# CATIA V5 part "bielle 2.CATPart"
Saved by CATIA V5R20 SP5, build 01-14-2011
Part number: bielle 2
Bounding box of the stored display mesh (mm): x -831.882 to 4290.352, y -250 to 250, z 2689.909 to 7173.528
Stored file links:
  M:\EU_thinkMotion\IAO_2010\iao\IAO_MMS_Groupe1\Problemes\gduval\Gduval\train d'aterrissage squelette + piece kinematic\bielle 2.CATPart
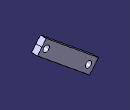
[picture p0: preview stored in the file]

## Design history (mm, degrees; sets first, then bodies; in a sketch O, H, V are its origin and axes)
Body1 (main body)
  Point1: stored without definition
  Point2: stored without definition
  Sketch1 on zx-plane, origin (0, 0, 0), H (-1, 0, 0), V (0, 0, 1)
    axis line L1 (-3755.1482, 6585.784) -> (369.2272, 3218.4199)
    reference projected point E1 (0, 3519.877) from Point1
    reference projected point E2 (-3562.187, 6428.24) from Point2
    line L2 (831.8815, 3594.3707) -> (-3551.9, 7173.5281)
    point P3 (831.8815, 3594.3707)
    point P4 (-3551.9, 7173.5281)
    line L3 (-3551.9, 7173.5281) -> (-3921.1258, 6721.2972)
    point P5 (-3921.1258, 6721.2972)
    line L4 (831.8815, 3594.3707) -> (462.6557, 3142.1398)
    point P6 (462.6557, 3142.1398)
    reference projected point E3 (0, 3519.877) from Point1
    reference projected point E4 (0, 3519.877) from Point1
    point P7 (-3921.1258, 6721.2972)
    point P8 (-4290.3517, 6269.0663)
    line L5 (-4290.3517, 6269.0663) -> (-3921.1258, 6721.2972)
    point P9 (93.4298, 2689.9089)
    line L6 (93.4298, 2689.9089) -> (-4290.3517, 6269.0663)
    point P10 (462.6557, 3142.1398)
    line L7 (93.4298, 2689.9089) -> (462.6557, 3142.1398)
    distance E3 L3 = 5062.0469
    distance L4 E4 = 597.2735
    distance L2 L1 = 583.8155
    coincidence: L1 E1, L1 E2, P5 L1, P6 L1, P5 P7, P6 P10
    perpendicularity: L3 L1, L4 L1
    symmetry: P5 P7 L1, P4 P8 L1, L3 L5 L1, P3 P9 L1, L2 L6 L1, P6 P10 L1, L4 L7 L1
  Pad1: profile Sketch1, direction (0, 1, 0), length 250, mirrored extent
  Sketch2 on start face of Pad1, origin (0, -250, 3519.877), H (1, 0, 0), V (0, 0, 1)
    point P1 (0, 0)
    reference projected point E1 (0, 0) from Point1
    coincidence: E1 P1
  Hole1: placed by Sketch2, at (0, -250, 3519.877) direction (0, 1, 0), diameter 520, through (limit type 6)
  Sketch3 on start face of Pad1, origin (3562.187, -250, 6428.24), H (1, 0, 0), V (0, 0, 1)
    point P1 (0, 0)
    reference projected point E1 (0, 0) from Point2
    coincidence: E1 P1
  Hole2: placed by Sketch3, at (3562.187, -250, 6428.24) direction (0, 1, 0), diameter 520, through (limit type 6)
